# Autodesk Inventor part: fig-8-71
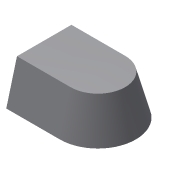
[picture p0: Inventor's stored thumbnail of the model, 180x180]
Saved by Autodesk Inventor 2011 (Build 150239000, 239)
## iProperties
Shininess: 77.0
Length Units: 11269
Angle Units: 11279
Time Units: 11290
Mass Units: 11283
Length Display Precision: 3
Angle Display Precision: 2
Created: 2002-01
Part Number: fig-8-71
Document SubType Name: Modeling
Designer: ***
Density: 1 g/cm^3
Density: 0.0
Volumn: 0.0
Area: 0.0
PropertySet Name: Model Information
Control State: 0
Master: False
Checked Out: False
Author: ***
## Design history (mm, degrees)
sketch "Sketch2"
  geometry: L1 (-19.86, 19.946)-(-19.86, -14.161); L2 (-19.86, -14.161)-(13.729, -14.161); L3 (13.729, 19.946)-(-19.86, 19.946); A1 r 17.054 centre (13.729, 2.893) between (13.729, -14.161) and (13.729, 19.946)
  constraints: 6 end point, 2 point on circle, 2 tangent, 1 centre point, 1 parallel, 1 perpendicular, 1 vertical
extrude "Extrusion2" new body sketch "Sketch2" distance "d6" = 25; taper "d7" = 0 deg
feature "FaceDraft8" dims angle "d14" = 15 deg
body "Solid1"
